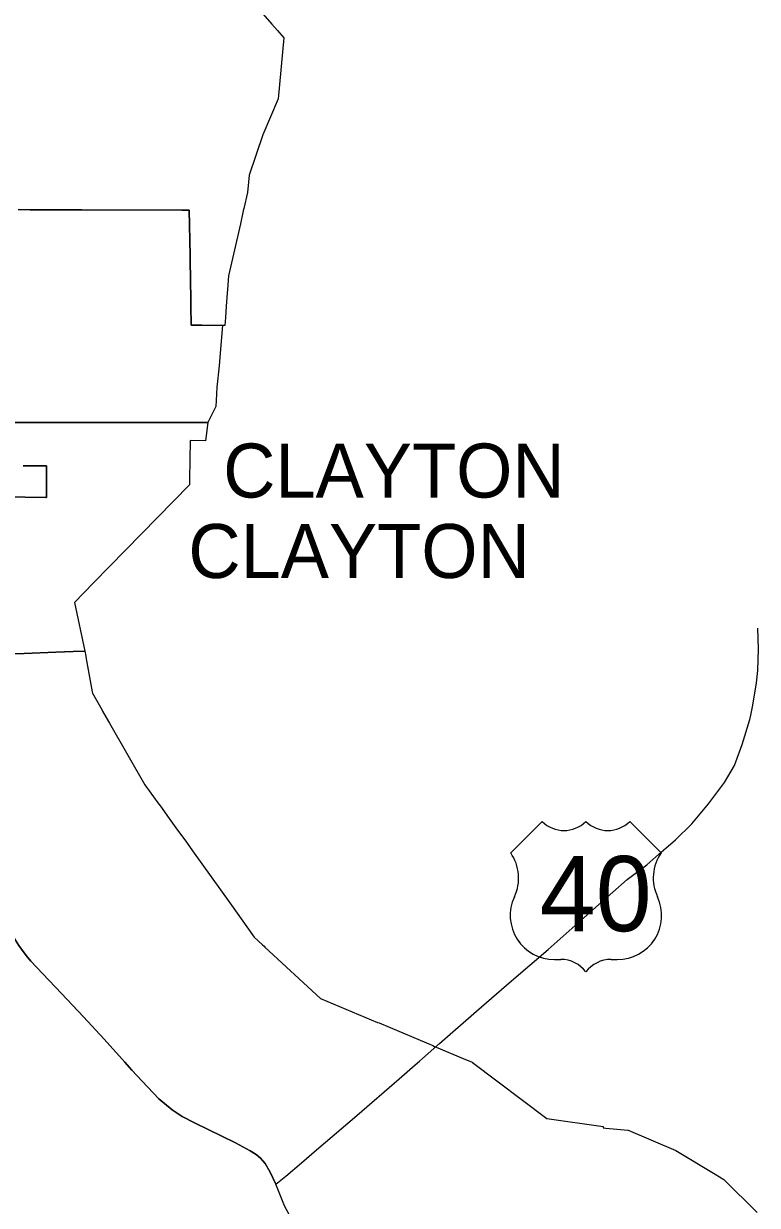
# Model space of a CAD drawing. Extents: x 0 to 34, y 0 to 22.
# Drawn here: x 4.8335 to 4.9426, y 15.8013 to 15.9771 of the extents above; entities that cross this region are included whole.
import ezdxf

# ---------------------------------------------------------------- set-up
doc = ezdxf.new("R2010")
doc.units = 0
for name, color, linetype in [('GM_X_Corporation', 7, 'Continuous'), ('GM_X_Corporation_Text', 7, 'Continuous'), ('GM_X_State_Route', 7, 'Continuous'), ('GM_X_US_Location', 7, 'Continuous'), ('GM_X_US_Route', 7, 'Continuous'), ('GM_X_US_Shield', 7, 'Continuous')]:
    doc.layers.add(name, color=color, linetype=linetype)

msp = doc.modelspace()

# ---------------------------------------------------------------- linework, layer by layer
at = {"layer": 'GM_X_Corporation'}
for points in [[(4.86732801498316, 15.98048374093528), (4.870376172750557, 15.977005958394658), (4.871194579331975, 15.976072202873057), (4.872133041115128, 15.975001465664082), (4.871292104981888, 15.965905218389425), (4.869025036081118, 15.960558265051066), (4.867015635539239, 15.954570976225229), (4.866730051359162, 15.951961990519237), (4.866198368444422, 15.949594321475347), (4.866121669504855, 15.949252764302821), (4.865683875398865, 15.94730306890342), (4.863947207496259, 15.939568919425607), (4.863789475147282, 15.937548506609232), (4.863745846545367, 15.936989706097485), (4.863596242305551, 15.935073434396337), (4.863461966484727, 15.93335351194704), (4.863369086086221, 15.93216379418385), (4.863229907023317, 15.932165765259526), (4.863014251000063, 15.932168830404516), (4.859974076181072, 15.93221248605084), (4.858384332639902, 15.932235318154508), (4.858335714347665, 15.935125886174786), (4.858325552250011, 15.935730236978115), (4.858309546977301, 15.936681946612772), (4.858282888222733, 15.938266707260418), (4.858210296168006, 15.942582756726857), (4.858096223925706, 15.94936529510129), (4.857178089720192, 15.949367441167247), (4.857005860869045, 15.949367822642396), (4.842103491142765, 15.949400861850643), (4.835353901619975, 15.949415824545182), (4.83444039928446, 15.949417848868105), (4.832666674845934, 15.949421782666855)], [(4.832666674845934, 15.949421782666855), (4.83444039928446, 15.949417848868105), (4.835353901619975, 15.949415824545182), (4.842103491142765, 15.949400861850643), (4.857005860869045, 15.949367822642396), (4.857178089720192, 15.949367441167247), (4.858096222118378, 15.949365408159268), (4.858210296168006, 15.942582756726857), (4.858282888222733, 15.938266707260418), (4.858309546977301, 15.936681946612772), (4.858325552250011, 15.935730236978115), (4.858335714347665, 15.935125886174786), (4.858384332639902, 15.932235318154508), (4.859974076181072, 15.93221248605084), (4.863014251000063, 15.932168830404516), (4.862641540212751, 15.927490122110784), (4.862538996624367, 15.926202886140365), (4.862204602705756, 15.923007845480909), (4.862080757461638, 15.921040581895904), (4.862022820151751, 15.920120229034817), (4.8618837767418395, 15.919837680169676), (4.86140467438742, 15.91886410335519), (4.860857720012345, 15.917752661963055), (4.85820128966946, 15.917755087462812), (4.854761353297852, 15.917758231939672), (4.838647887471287, 15.917772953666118), (4.836753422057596, 15.917774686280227), (4.834143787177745, 15.917777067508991), (4.832108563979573, 15.917778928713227)], [(4.832108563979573, 15.917778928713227), (4.834143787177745, 15.917777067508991), (4.836753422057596, 15.917774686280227), (4.838647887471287, 15.917772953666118), (4.854761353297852, 15.917758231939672), (4.85820128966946, 15.917755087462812), (4.860857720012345, 15.917752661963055), (4.8605043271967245, 15.91503645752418), (4.858202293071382, 15.915058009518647), (4.858149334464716, 15.909350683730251), (4.858146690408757, 15.909060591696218), (4.8581415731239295, 15.908499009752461), (4.843850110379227, 15.893888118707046), (4.841019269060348, 15.890994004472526), (4.842564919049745, 15.883763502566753), (4.840817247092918, 15.883692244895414), (4.838247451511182, 15.88358746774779), (4.833542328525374, 15.883395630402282), (4.830730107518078, 15.883280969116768)], [(4.833394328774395, 15.91131844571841), (4.836849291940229, 15.91129423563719), (4.836883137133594, 15.91129399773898), (4.8368578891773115, 15.906610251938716), (4.836762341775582, 15.90661091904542), (4.8336865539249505, 15.906632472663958), (4.826505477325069, 15.906682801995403)], [(4.826505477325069, 15.906682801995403), (4.8336865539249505, 15.906632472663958), (4.836762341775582, 15.90661091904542), (4.8368578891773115, 15.906610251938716), (4.836849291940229, 15.91129423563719), (4.833394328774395, 15.91131844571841)], [(4.830730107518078, 15.883280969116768), (4.833542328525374, 15.883395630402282), (4.838247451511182, 15.88358746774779), (4.84083844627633, 15.883693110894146), (4.842564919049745, 15.883763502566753), (4.84262610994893, 15.883477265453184), (4.842664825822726, 15.88329614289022), (4.842785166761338, 15.88261067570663), (4.843652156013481, 15.877672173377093), (4.843684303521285, 15.877489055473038), (4.845070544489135, 15.875064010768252), (4.8452040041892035, 15.874830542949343), (4.846079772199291, 15.873298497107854), (4.846217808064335, 15.87305702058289), (4.8514657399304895, 15.86387646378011), (4.851465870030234, 15.863876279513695), (4.853406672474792, 15.861202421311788), (4.85379304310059, 15.860670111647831), (4.855114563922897, 15.858849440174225), (4.856114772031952, 15.857471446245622), (4.857684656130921, 15.855308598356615), (4.858580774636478, 15.854051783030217), (4.86410747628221, 15.846300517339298), (4.867740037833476, 15.84120580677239), (4.8689862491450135, 15.840058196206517), (4.8692227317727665, 15.839840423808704), (4.869342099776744, 15.839730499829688), (4.877614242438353, 15.832097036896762), (4.886096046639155, 15.828527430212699), (4.886320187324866, 15.828433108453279), (4.887946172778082, 15.827748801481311), (4.894329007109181, 15.825062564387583), (4.894574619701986, 15.824959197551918), (4.894824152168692, 15.82485417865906), (4.89882862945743, 15.823168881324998), (4.900173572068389, 15.822602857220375), (4.900177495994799, 15.822601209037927), (4.900209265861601, 15.82257721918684), (4.900224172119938, 15.822565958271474), (4.911245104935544, 15.814243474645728), (4.919622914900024, 15.813044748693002), (4.91962313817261, 15.812825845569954), (4.920012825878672, 15.812810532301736), (4.923305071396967, 15.81248576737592), (4.923335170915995, 15.812472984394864), (4.9304133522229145, 15.809467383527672), (4.936288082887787, 15.805923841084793), (4.937571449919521, 15.805149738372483), (4.942506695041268, 15.80026118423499)]]:
    msp.add_lwpolyline(points, dxfattribs=at)
at = {"layer": 'GM_X_State_Route'}
for points in [[(4.864988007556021, 15.810628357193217), (4.858863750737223, 15.813592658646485), (4.857039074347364, 15.81452820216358), (4.855561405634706, 15.815516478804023), (4.853586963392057, 15.817147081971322), (4.851081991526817, 15.819793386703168), (4.849531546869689, 15.821406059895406), (4.848529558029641, 15.822596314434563), (4.845429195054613, 15.826009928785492), (4.842344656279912, 15.829329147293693), (4.839079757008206, 15.832797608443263), (4.836315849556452, 15.835725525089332), (4.834551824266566, 15.837624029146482), (4.833854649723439, 15.838495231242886), (4.833121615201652, 15.839420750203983), (4.832761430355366, 15.839953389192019), (4.831764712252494, 15.841528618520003), (4.830733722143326, 15.843108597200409), (4.828572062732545, 15.846547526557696), (4.825308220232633, 15.851501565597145), (4.824820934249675, 15.85229849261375)], [(4.870982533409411, 15.804437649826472), (4.870130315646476, 15.806261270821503), (4.8693550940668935, 15.807548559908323), (4.868681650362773, 15.808315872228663), (4.86801664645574, 15.808875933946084), (4.867131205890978, 15.809411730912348), (4.864988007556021, 15.810628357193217)], [(4.887960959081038, 15.782940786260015), (4.885214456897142, 15.785879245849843), (4.883214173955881, 15.788073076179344), (4.88224066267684, 15.789100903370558), (4.881530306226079, 15.789851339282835), (4.879577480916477, 15.791953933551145), (4.875763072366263, 15.796179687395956), (4.874326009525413, 15.79779869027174), (4.873300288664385, 15.799289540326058), (4.872257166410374, 15.801254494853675), (4.870982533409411, 15.804437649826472)]]:
    msp.add_lwpolyline(points, dxfattribs=at)
at = {"layer": 'GM_X_US_Route'}
for p, q in [((4.9287233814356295, 15.854240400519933), (4.928930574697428, 15.854421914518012)), ((4.9285852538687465, 15.85411939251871), (4.9287233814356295, 15.854240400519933)), ((4.872431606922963, 15.805666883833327), (4.874762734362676, 15.807644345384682)), ((4.870982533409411, 15.804437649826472), (4.872431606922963, 15.805666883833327))]:
    msp.add_line(p, q, dxfattribs=at)
for points in [[(4.9415652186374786, 15.874230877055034), (4.941895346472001, 15.875706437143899), (4.942431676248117, 15.879027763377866), (4.942620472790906, 15.88088354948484), (4.942713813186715, 15.88407356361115), (4.942624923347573, 15.887176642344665)], [(4.928930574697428, 15.854421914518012), (4.930380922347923, 15.855692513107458), (4.93281311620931, 15.858071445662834), (4.9352874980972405, 15.861030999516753), (4.937669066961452, 15.864185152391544), (4.939135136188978, 15.86674180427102), (4.940320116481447, 15.869852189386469), (4.941418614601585, 15.8735769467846), (4.9415652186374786, 15.874230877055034)], [(4.892308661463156, 15.82276885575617), (4.892750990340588, 15.82315320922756), (4.895311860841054, 15.825378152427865), (4.900806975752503, 15.830195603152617), (4.90600729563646, 15.834726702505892), (4.911434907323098, 15.83938383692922), (4.916799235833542, 15.844106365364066), (4.9232114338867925, 15.849780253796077), (4.926134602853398, 15.851971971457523), (4.9279091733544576, 15.853526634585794), (4.9285852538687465, 15.85411939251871)], [(4.824820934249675, 15.85229849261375), (4.825308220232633, 15.851501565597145), (4.828572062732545, 15.846547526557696), (4.830733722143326, 15.843108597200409), (4.831764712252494, 15.841528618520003), (4.832761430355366, 15.839953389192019), (4.833121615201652, 15.839420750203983), (4.833854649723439, 15.838495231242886), (4.834551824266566, 15.837624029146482), (4.836315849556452, 15.835725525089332), (4.839079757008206, 15.832797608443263), (4.842344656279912, 15.829329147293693), (4.845429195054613, 15.826009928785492), (4.848529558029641, 15.822596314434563), (4.849531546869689, 15.821406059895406), (4.851081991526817, 15.819793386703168), (4.853586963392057, 15.817147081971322), (4.855561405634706, 15.815516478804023), (4.857039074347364, 15.81452820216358), (4.858863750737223, 15.813592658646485), (4.864988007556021, 15.810628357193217)], [(4.874762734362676, 15.807644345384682), (4.877030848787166, 15.809568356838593), (4.883014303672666, 15.814667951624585), (4.889294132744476, 15.82014988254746), (4.891676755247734, 15.822219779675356), (4.892308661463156, 15.82276885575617)], [(4.864988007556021, 15.810628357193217), (4.867131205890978, 15.809411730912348), (4.86801664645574, 15.808875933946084), (4.868681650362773, 15.808315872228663), (4.8693550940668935, 15.807548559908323), (4.870130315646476, 15.806261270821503), (4.870982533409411, 15.804437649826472)]]:
    msp.add_lwpolyline(points, dxfattribs=at)
at = {"layer": 'GM_X_US_Shield'}
for p, q in [((4.910543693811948, 15.858400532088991), (4.9058815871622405, 15.85373842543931)), ((4.9282596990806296, 15.85373842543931), (4.923597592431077, 15.858400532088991)), ((4.912408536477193, 15.837887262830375), (4.913340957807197, 15.837887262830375)), ((4.920800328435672, 15.837887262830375), (4.921732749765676, 15.837887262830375))]:
    msp.add_line(p, q, dxfattribs=at)
for centre, radius, start, end in [((4.913807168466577, 15.861729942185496), 0.004662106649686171, 225.57299599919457, 314.4270040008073), ((4.920334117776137, 15.861729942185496), 0.004662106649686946, 225.57299599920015, 314.4270040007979), ((4.900535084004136, 15.84999463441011), 0.006526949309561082, 334.5471236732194, 35.000929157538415), ((4.933606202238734, 15.84999463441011), 0.006526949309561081, 144.99907084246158, 205.4528763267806), ((4.912335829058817, 15.844413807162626), 0.006526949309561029, 154.8319194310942, 270.63826363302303), ((4.921805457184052, 15.844413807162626), 0.006526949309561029, 269.36173636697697, 25.168080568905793), ((4.913340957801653, 15.833225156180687), 0.0046621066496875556, 36.86989764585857, 89.99999993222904), ((4.920800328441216, 15.833225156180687), 0.0046621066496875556, 90.00000006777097, 143.13010235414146)]:
    msp.add_arc(centre, radius, start, end, dxfattribs=at)

# ---------------------------------------------------------------- texts
at = {"layer": 'GM_X_Corporation_Text'}
for p in [(4.863132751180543, 15.906592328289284), (4.857957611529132, 15.894623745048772)]:
    msp.add_text('CLAYTON', height=0.008037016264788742, rotation=1.0000000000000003e-05, dxfattribs=at).set_placement(p)
at = {"layer": 'GM_X_US_Location'}
for s, p in [('0', (4.917064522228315, 15.847589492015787)), ('/', (4.917066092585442, 15.847589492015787))]:
    msp.add_text(s, height=1.6074032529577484e-05, dxfattribs=at).set_placement(p)
msp.add_text('40', height=1.6074032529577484e-05, rotation=1.0000000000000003e-05, dxfattribs=at).set_placement((4.913746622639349, 15.844262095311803))
at = {"layer": 'GM_X_US_Shield'}
msp.add_text('40', height=0.011189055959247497, dxfattribs=at).set_placement((4.910204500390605, 15.842083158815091))

doc.saveas('drawing.dxf')
